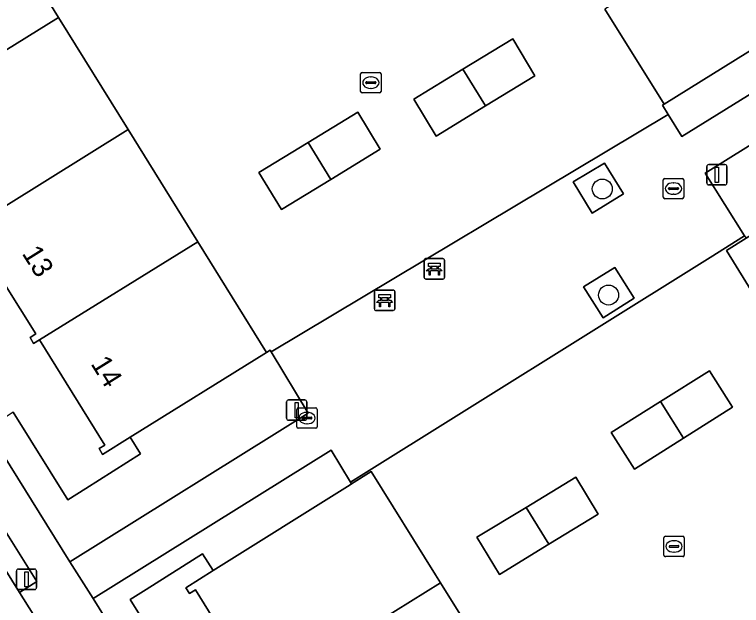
# Model space of a CAD drawing. Extents: x 159279 to 160377, y 384531 to 385888.
# Drawn here: x 159510.12 to 159545.75, y 385344.02 to 385373 of the extents above; entities that cross this region are included whole.
import ezdxf

# ---------------------------------------------------------------- set-up
doc = ezdxf.new("R2010")
doc.units = 0
for name, color, linetype in [('IMGEO_Bank', 7, 'Continuous'), ('IMGEO_Boom', 7, 'Continuous'), ('IMGEO_Erf', 7, 'Continuous'), ('IMGEO_Groenvoorziening', 7, 'Continuous'), ('IMGEO_Kolk', 7, 'Continuous'), ('IMGEO_Lichtmast', 7, 'Continuous'), ('IMGEO_Pand', 7, 'Continuous'), ('IMGEO_Pand_nummerreeks', 7, 'Continuous'), ('IMGEO_Rijbaan_lokaal_open', 7, 'Continuous'), ('IMGEO_Terreindeel_gesloten', 7, 'Continuous'), ('IMGEO_Voetpad_open', 7, 'Continuous')]:
    doc.layers.add(name, color=color, linetype=linetype)

msp = doc.modelspace()

# ---------------------------------------------------------------- linework, layer by layer
at = {"layer": 'IMGEO_Bank'}
for p, q in [((159530.199, 385360.104), (159530.199, 385360.945)), ((159530.199, 385360.945), (159530.199, 385360.104)), ((159530.274, 385361.029), (159531.115, 385361.029)), ((159531.115, 385361.029), (159530.274, 385361.029)), ((159531.199, 385360.954), (159531.199, 385360.113)), ((159531.199, 385360.113), (159531.199, 385360.954)), ((159530.896, 385360.427), (159530.503, 385360.427)), ((159530.508, 385360.535), (159530.508, 385360.641)), ((159530.552, 385360.641), (159530.552, 385360.535)), ((159530.84, 385360.647), (159530.558, 385360.647)), ((159530.558, 385360.529), (159530.84, 385360.529)), ((159530.846, 385360.535), (159530.846, 385360.641)), ((159530.89, 385360.641), (159530.89, 385360.535)), ((159531.124, 385360.029), (159530.283, 385360.029)), ((159530.283, 385360.029), (159531.124, 385360.029)), ((159527.764, 385358.564), (159527.764, 385359.405)), ((159527.764, 385359.405), (159527.764, 385358.564)), ((159527.839, 385359.489), (159528.68, 385359.489)), ((159528.68, 385359.489), (159527.839, 385359.489)), ((159528.764, 385359.414), (159528.764, 385358.573)), ((159528.764, 385358.573), (159528.764, 385359.414)), ((159528.073, 385358.995), (159528.073, 385359.101)), ((159528.117, 385359.101), (159528.117, 385358.995)), ((159528.405, 385359.107), (159528.123, 385359.107)), ((159528.123, 385358.989), (159528.405, 385358.989)), ((159528.411, 385358.995), (159528.411, 385359.101)), ((159528.455, 385359.101), (159528.455, 385358.995)), ((159528.461, 385358.887), (159528.068, 385358.887)), ((159528.689, 385358.489), (159527.848, 385358.489)), ((159527.848, 385358.489), (159528.689, 385358.489))]:
    msp.add_line(p, q, dxfattribs=at)
for points in [[(159530.502, 385360.647), (159530.416, 385360.647), (159530.416, 385360.808), (159530.979, 385360.808), (159530.979, 385360.647), (159530.896, 385360.647)], [(159530.446, 385360.427), (159530.304, 385360.427), (159530.416, 385360.529), (159530.502, 385360.529)], [(159530.496, 385360.42), (159530.496, 385360.213), (159530.453, 385360.213), (159530.453, 385360.42)], [(159530.896, 385360.529), (159530.979, 385360.529), (159531.091, 385360.427), (159530.952, 385360.427)], [(159530.946, 385360.42), (159530.946, 385360.213), (159530.902, 385360.213), (159530.902, 385360.42)], [(159528.067, 385359.107), (159527.981, 385359.107), (159527.981, 385359.268), (159528.544, 385359.268), (159528.544, 385359.107), (159528.461, 385359.107)], [(159528.011, 385358.887), (159527.869, 385358.887), (159527.981, 385358.989), (159528.067, 385358.989)], [(159528.461, 385358.989), (159528.544, 385358.989), (159528.656, 385358.887), (159528.517, 385358.887)], [(159528.061, 385358.88), (159528.061, 385358.673), (159528.018, 385358.673), (159528.018, 385358.88)], [(159528.511, 385358.88), (159528.511, 385358.673), (159528.467, 385358.673), (159528.467, 385358.88)]]:
    msp.add_lwpolyline(points, dxfattribs=at)
for centre, radius, start, end in [((159530.277, 385360.951), 0.0779, 92.4484, 184.2845), ((159530.277, 385360.951), 0.0779, 92.4484, 184.2845), ((159531.121, 385360.951), 0.0779, 2.4484, 94.2845), ((159531.121, 385360.951), 0.0779, 2.4484, 94.2845), ((159530.446, 385360.42), 0.00671, 2.8957, 87.1043), ((159530.503, 385360.42), 0.00671, 92.8957, 177.1043), ((159530.501, 385360.64), 0.00671, 2.8957, 87.1043), ((159530.501, 385360.536), 0.00671, 272.8957, 357.1043), ((159530.558, 385360.64), 0.00671, 92.8957, 177.1043), ((159530.558, 385360.536), 0.00671, 182.8957, 267.1043), ((159530.84, 385360.64), 0.00671, 2.8957, 87.1043), ((159530.84, 385360.536), 0.00671, 272.8957, 357.1043), ((159530.897, 385360.64), 0.00671, 92.8957, 177.1043), ((159530.897, 385360.536), 0.00671, 182.8957, 267.1043), ((159530.895, 385360.42), 0.00671, 2.8957, 87.1043), ((159530.952, 385360.42), 0.00671, 92.8957, 177.1043), ((159530.277, 385360.107), 0.0779, 182.4484, 274.2845), ((159530.277, 385360.107), 0.0779, 182.4484, 274.2845), ((159531.121, 385360.107), 0.0779, 272.4484, 4.2845), ((159531.121, 385360.107), 0.0779, 272.4484, 4.2845), ((159527.842, 385359.411), 0.0779, 92.4484, 184.2845), ((159527.842, 385359.411), 0.0779, 92.4484, 184.2845), ((159528.686, 385359.411), 0.0779, 2.4484, 94.2845), ((159528.686, 385359.411), 0.0779, 2.4484, 94.2845), ((159528.066, 385359.1), 0.00671, 2.8957, 87.1043), ((159528.066, 385358.996), 0.00671, 272.8957, 357.1043), ((159528.123, 385359.1), 0.00671, 92.8957, 177.1043), ((159528.123, 385358.996), 0.00671, 182.8957, 267.1043), ((159528.405, 385359.1), 0.00671, 2.8957, 87.1043), ((159528.405, 385358.996), 0.00671, 272.8957, 357.1043), ((159528.462, 385359.1), 0.00671, 92.8957, 177.1043), ((159528.462, 385358.996), 0.00671, 182.8957, 267.1043), ((159527.842, 385358.567), 0.0779, 182.4484, 274.2845), ((159527.842, 385358.567), 0.0779, 182.4484, 274.2845), ((159528.011, 385358.88), 0.00671, 2.8957, 87.1043), ((159528.068, 385358.88), 0.00671, 92.8957, 177.1043), ((159528.46, 385358.88), 0.00671, 2.8957, 87.1043), ((159528.517, 385358.88), 0.00671, 92.8957, 177.1043), ((159528.686, 385358.567), 0.0779, 272.4484, 4.2845), ((159528.686, 385358.567), 0.0779, 272.4484, 4.2845)]:
    msp.add_arc(centre, radius, start, end, dxfattribs=at)
at = {"layer": 'IMGEO_Boom'}
for centre in [(159538.932, 385364.446), (159539.24, 385359.245)]:
    msp.add_circle(centre, 0.489, dxfattribs=at)
at = {"layer": 'IMGEO_Erf'}
for points in [[(159508.971, 385378.179), (159512.272, 385372.863), (159515.691, 385367.355), (159519.102, 385361.861), (159522.472, 385356.434), (159522.653, 385356.547), (159522.704, 385356.461), (159542.167, 385368.097), (159541.884, 385368.557), (159541.969, 385368.61), (159539.064, 385373.265)], [(159510.061, 385353.497), (159512.737, 385349.205), (159513.619, 385349.761), (159516.301, 385351.454), (159515.795, 385352.272), (159514.431, 385351.421), (159514.264, 385351.717), (159514.545, 385351.888), (159511.339, 385357.041), (159511.055, 385356.868), (159510.882, 385357.158), (159511.164, 385357.337), (159508.002, 385362.379)], [(159545.911, 385362.141), (159544.219, 385361.084), (159526.589, 385350.077), (159526.643, 385349.992), (159527.598, 385350.585), (159530.751, 385345.531), (159530.995, 385345.14), (159534.332, 385339.79), (159537.665, 385334.447), (159541.091, 385328.956), (159544.511, 385323.473), (159547.84, 385318.137)], [(159546.45, 385359.131), (159545.022, 385361.424), (159545.983, 385362.027)]]:
    msp.add_lwpolyline(points, dxfattribs=at)
for points in [[(159532.101, 385370.326), (159534.539, 385371.81), (159535.626, 385369.995), (159533.211, 385368.516), (159530.795, 385367.036), (159529.689, 385368.858)], [(159524.515, 385366.729), (159526.953, 385368.213), (159528.04, 385366.398), (159525.625, 385364.919), (159523.209, 385363.439), (159522.103, 385365.261)], [(159540.509, 385350.712), (159539.375, 385352.511), (159541.785, 385354.025), (159544.186, 385355.533), (159545.323, 385353.739), (159542.916, 385352.226)], [(159538.724, 385348.503), (159536.308, 385347.024), (159533.893, 385345.544), (159532.787, 385347.366), (159535.199, 385348.834), (159537.637, 385350.318)]]:
    msp.add_lwpolyline(points, close=True, dxfattribs=at)
at = {"layer": 'IMGEO_Groenvoorziening'}
for points in [[(159552.306, 385379.406), (159549.83, 385377.84), (159551.76, 385374.716), (159550.773, 385374.1), (159541.969, 385368.61), (159541.884, 385368.557), (159542.167, 385368.097), (159542.83, 385367.018), (159555.238, 385374.72)], [(159556.351, 385372.911), (159552.599, 385370.593), (159543.979, 385365.226), (159545.911, 385362.141), (159545.983, 385362.027), (159549.656, 385364.332), (159554.867, 385367.58), (159555.774, 385368.145), (159557.757, 385364.996), (159560.291, 385366.59)], [(159539.04, 385365.72), (159537.509, 385364.793), (159538.438, 385363.263), (159539.974, 385364.206)], [(159539.549, 385360.593), (159538.008, 385359.643), (159538.98, 385358.125), (159540.493, 385359.091)], [(159503.017, 385356.459), (159510.367, 385344.653), (159511.207, 385345.192), (159503.848, 385356.959)], [(159522.704, 385356.461), (159522.653, 385356.547), (159522.472, 385356.434), (159515.795, 385352.272), (159516.301, 385351.454), (159513.619, 385349.761), (159512.737, 385349.205), (159510.061, 385353.497), (159509.655, 385353.244), (159508.766, 385352.691), (159512.828, 385346.166), (159524.507, 385353.448)], [(159526.567, 385349.945), (159526.643, 385349.992), (159526.589, 385350.077), (159525.637, 385351.642), (159513.967, 385344.361), (159516.864, 385339.703), (159517.725, 385340.259), (159518.148, 385340.532), (159516.872, 385342.583), (159515.793, 385344.318), (159516.58, 385344.813), (159519.338, 385346.547), (159519.862, 385345.731)]]:
    msp.add_lwpolyline(points, close=True, dxfattribs=at)
at = {"layer": 'IMGEO_Kolk'}
for p, q in [((159527.086, 385369.234), (159527.086, 385370.086)), ((159527.161, 385370.16), (159528.013, 385370.16)), ((159528.087, 385370.086), (159528.087, 385369.234)), ((159527.345, 385369.654), (159527.345, 385369.666)), ((159527.783, 385369.617), (159527.385, 385369.617)), ((159527.388, 385369.703), (159527.786, 385369.703)), ((159527.574, 385369.94), (159527.599, 385369.94)), ((159527.829, 385369.666), (159527.829, 385369.654)), ((159527.597, 385369.38), (159527.572, 385369.38)), ((159528.013, 385369.16), (159527.161, 385369.16)), ((159541.997, 385364.967), (159542.849, 385364.967)), ((159541.922, 385364.041), (159541.922, 385364.893)), ((159542.41, 385364.747), (159542.435, 385364.747)), ((159542.923, 385364.893), (159542.923, 385364.041)), ((159542.181, 385364.461), (159542.181, 385364.473)), ((159542.619, 385364.424), (159542.221, 385364.424)), ((159542.224, 385364.51), (159542.622, 385364.51)), ((159542.665, 385364.473), (159542.665, 385364.461)), ((159542.849, 385363.967), (159541.997, 385363.967)), ((159542.433, 385364.187), (159542.408, 385364.187)), ((159523.955, 385352.787), (159523.955, 385353.639)), ((159524.03, 385353.713), (159524.882, 385353.713)), ((159524.956, 385353.639), (159524.956, 385352.787)), ((159524.214, 385353.207), (159524.214, 385353.219)), ((159524.257, 385353.256), (159524.655, 385353.256)), ((159524.443, 385353.493), (159524.468, 385353.493)), ((159524.698, 385353.219), (159524.698, 385353.207)), ((159524.652, 385353.17), (159524.254, 385353.17)), ((159524.466, 385352.933), (159524.441, 385352.933)), ((159524.882, 385352.713), (159524.03, 385352.713)), ((159541.949, 385346.49), (159541.949, 385347.342)), ((159542.024, 385347.416), (159542.876, 385347.416)), ((159542.437, 385347.196), (159542.462, 385347.196)), ((159542.95, 385347.342), (159542.95, 385346.49)), ((159542.208, 385346.91), (159542.208, 385346.922)), ((159542.646, 385346.873), (159542.248, 385346.873)), ((159542.251, 385346.959), (159542.649, 385346.959)), ((159542.692, 385346.922), (159542.692, 385346.91)), ((159542.46, 385346.636), (159542.435, 385346.636)), ((159542.876, 385346.416), (159542.024, 385346.416))]:
    msp.add_line(p, q, dxfattribs=at)
for points in [[(159527.086, 385369.234), (159527.086, 385370.086)], [(159527.161, 385370.16), (159528.013, 385370.16)], [(159528.087, 385370.086), (159528.087, 385369.234)], [(159528.013, 385369.16), (159527.161, 385369.16)], [(159541.997, 385364.967), (159542.849, 385364.967)], [(159541.922, 385364.041), (159541.922, 385364.893)], [(159542.923, 385364.893), (159542.923, 385364.041)], [(159542.849, 385363.967), (159541.997, 385363.967)], [(159523.955, 385352.787), (159523.955, 385353.639)], [(159524.03, 385353.713), (159524.882, 385353.713)], [(159524.956, 385353.639), (159524.956, 385352.787)], [(159524.882, 385352.713), (159524.03, 385352.713)], [(159541.949, 385346.49), (159541.949, 385347.342)], [(159542.024, 385347.416), (159542.876, 385347.416)], [(159542.95, 385347.342), (159542.95, 385346.49)], [(159542.876, 385346.416), (159542.024, 385346.416)]]:
    msp.add_lwpolyline(points, dxfattribs=at)
for centre, radius, start, end in [((159527.163, 385370.084), 0.0765, 91.552, 178.448), ((159527.163, 385370.084), 0.0765, 91.552, 178.448), ((159528.011, 385370.084), 0.0765, 1.552, 88.448), ((159528.011, 385370.084), 0.0765, 1.552, 88.448), ((159527.385, 385369.663), 0.0403, 85.8775, 175.7526), ((159527.382, 385369.653), 0.0366, 178.938, 274.7102), ((159527.786, 385369.66), 0.043, 264.8664, 352.4533), ((159527.79, 385369.665), 0.0386, 1.7309, 96.639), ((159527.163, 385369.236), 0.0765, 181.552, 268.448), ((159527.163, 385369.236), 0.0765, 181.552, 268.448), ((159528.011, 385369.236), 0.0765, 271.552, 358.448), ((159528.011, 385369.236), 0.0765, 271.552, 358.448), ((159541.999, 385364.891), 0.0765, 91.552, 178.448), ((159541.999, 385364.891), 0.0765, 91.552, 178.448), ((159542.847, 385364.891), 0.0765, 1.552, 88.448), ((159542.847, 385364.891), 0.0765, 1.552, 88.448), ((159542.221, 385364.47), 0.0403, 85.8775, 175.7526), ((159542.218, 385364.46), 0.0366, 178.938, 274.7102), ((159542.622, 385364.467), 0.043, 264.8664, 352.4533), ((159542.626, 385364.472), 0.0386, 1.7309, 96.639), ((159541.999, 385364.043), 0.0765, 181.552, 268.448), ((159541.999, 385364.043), 0.0765, 181.552, 268.448), ((159542.847, 385364.043), 0.0765, 271.552, 358.448), ((159542.847, 385364.043), 0.0765, 271.552, 358.448), ((159524.032, 385353.637), 0.0765, 91.552, 178.448), ((159524.032, 385353.637), 0.0765, 91.552, 178.448), ((159524.88, 385353.637), 0.0765, 1.552, 88.448), ((159524.88, 385353.637), 0.0765, 1.552, 88.448), ((159524.254, 385353.216), 0.0403, 85.8775, 175.7526), ((159524.251, 385353.206), 0.0366, 178.938, 274.7102), ((159524.655, 385353.213), 0.043, 264.8664, 352.4533), ((159524.659, 385353.218), 0.0386, 1.7309, 96.639), ((159524.032, 385352.789), 0.0765, 181.552, 268.448), ((159524.032, 385352.789), 0.0765, 181.552, 268.448), ((159524.88, 385352.789), 0.0765, 271.552, 358.448), ((159524.88, 385352.789), 0.0765, 271.552, 358.448), ((159542.026, 385347.34), 0.0765, 91.552, 178.448), ((159542.026, 385347.34), 0.0765, 91.552, 178.448), ((159542.874, 385347.34), 0.0765, 1.552, 88.448), ((159542.874, 385347.34), 0.0765, 1.552, 88.448), ((159542.248, 385346.919), 0.0403, 85.8775, 175.7526), ((159542.245, 385346.909), 0.0366, 178.938, 274.7102), ((159542.649, 385346.916), 0.043, 264.8664, 352.4533), ((159542.653, 385346.921), 0.0386, 1.7309, 96.639), ((159542.026, 385346.492), 0.0765, 181.552, 268.448), ((159542.026, 385346.492), 0.0765, 181.552, 268.448), ((159542.874, 385346.492), 0.0765, 271.552, 358.448), ((159542.874, 385346.492), 0.0765, 271.552, 358.448)]:
    msp.add_arc(centre, radius, start, end, dxfattribs=at)
for centre, major_axis, ratio, start_param, end_param in [((159527.573, 385369.66), (-0.387, 0.002), 0.722429, 4.712389, 7.853982), ((159527.598, 385369.66), (-0.39, 0.002), 0.717154, 1.570796, 4.712389), ((159542.409, 385364.467), (-0.387, 0.002), 0.722429, 4.712389, 7.853982), ((159542.434, 385364.467), (-0.39, 0.002), 0.717154, 1.570796, 4.712389), ((159524.442, 385353.213), (-0.387, 0.002), 0.722429, 4.712389, 7.853982), ((159524.467, 385353.213), (-0.39, 0.002), 0.717154, 1.570796, 4.712389), ((159542.436, 385346.916), (-0.387, 0.002), 0.722429, 4.712389, 7.853982), ((159542.461, 385346.916), (-0.39, 0.002), 0.717154, 1.570796, 4.712389)]:
    msp.add_ellipse(centre, major_axis=major_axis, ratio=ratio, start_param=start_param, end_param=end_param, dxfattribs=at)
at = {"layer": 'IMGEO_Lichtmast'}
for p, q in [((159544.053, 385364.745), (159544.053, 385365.545)), ((159544.053, 385365.545), (159544.053, 385364.745)), ((159544.153, 385365.645), (159544.943, 385365.645)), ((159544.943, 385365.645), (159544.153, 385365.645)), ((159545.043, 385365.545), (159545.043, 385364.745)), ((159545.043, 385364.745), (159545.043, 385365.545)), ((159544.943, 385364.645), (159544.153, 385364.645)), ((159544.153, 385364.645), (159544.943, 385364.645)), ((159523.458, 385353.202), (159523.458, 385354.002)), ((159523.458, 385354.002), (159523.458, 385353.202)), ((159523.558, 385354.102), (159524.348, 385354.102)), ((159524.348, 385354.102), (159523.558, 385354.102)), ((159524.448, 385354.002), (159524.448, 385353.202)), ((159524.448, 385353.202), (159524.448, 385354.002)), ((159524.348, 385353.102), (159523.558, 385353.102)), ((159523.558, 385353.102), (159524.348, 385353.102)), ((159510.311, 385345.805), (159511.101, 385345.805)), ((159511.101, 385345.805), (159510.311, 385345.805)), ((159510.211, 385344.905), (159510.211, 385345.705)), ((159510.211, 385345.705), (159510.211, 385344.905)), ((159511.201, 385345.705), (159511.201, 385344.905)), ((159511.201, 385344.905), (159511.201, 385345.705)), ((159511.101, 385344.805), (159510.311, 385344.805)), ((159510.311, 385344.805), (159511.101, 385344.805))]:
    msp.add_line(p, q, dxfattribs=at)
for points in [[(159544.473, 385365.52), (159544.623, 385365.52), (159544.623, 385364.77), (159544.473, 385364.77), (159544.473, 385365.52)], [(159523.878, 385353.977), (159524.028, 385353.977), (159524.028, 385353.227), (159523.878, 385353.227), (159523.878, 385353.977)], [(159510.631, 385345.68), (159510.781, 385345.68), (159510.781, 385344.93), (159510.631, 385344.93), (159510.631, 385345.68)]]:
    msp.add_lwpolyline(points, dxfattribs=at)
for centre, start, end in [((159544.153, 385365.545), 90, 180), ((159544.153, 385365.545), 90, 180), ((159544.943, 385365.545), 0, 90), ((159544.943, 385365.545), 360, 90), ((159544.153, 385364.745), 180, 270), ((159544.153, 385364.745), 180, 270), ((159544.943, 385364.745), 270, 0), ((159544.943, 385364.745), 270, 0), ((159523.558, 385354.002), 90, 180), ((159523.558, 385354.002), 90, 180), ((159524.348, 385354.002), 0, 90), ((159524.348, 385354.002), 360, 90), ((159523.558, 385353.202), 180, 270), ((159523.558, 385353.202), 180, 270), ((159524.348, 385353.202), 270, 0), ((159524.348, 385353.202), 270, 0), ((159510.311, 385345.705), 90, 180), ((159510.311, 385345.705), 90, 180), ((159511.101, 385345.705), 0, 90), ((159511.101, 385345.705), 360, 90), ((159510.311, 385344.905), 180, 270), ((159510.311, 385344.905), 180, 270), ((159511.101, 385344.905), 270, 0), ((159511.101, 385344.905), 270, 0)]:
    msp.add_arc(centre, 0.1, start, end, dxfattribs=at)
at = {"layer": 'IMGEO_Pand'}
for points in [[(159550.773, 385374.1), (159549.19, 385376.653), (159549.47, 385376.825), (159549.29, 385377.084), (159549.012, 385376.913), (159547.857, 385378.754), (159539.064, 385373.265), (159541.969, 385368.61)], [(159508.971, 385378.179), (159501.165, 385373.333), (159500.904, 385373.164), (159501.059, 385372.896), (159501.33, 385373.071), (159504.502, 385368.039), (159512.272, 385372.863)], [(159512.272, 385372.863), (159504.502, 385368.039), (159504.212, 385367.85), (159504.374, 385367.579), (159504.651, 385367.741), (159507.83, 385362.678), (159507.547, 385362.501), (159507.634, 385362.352), (159515.691, 385367.355)], [(159532.101, 385370.326), (159533.211, 385368.516), (159535.626, 385369.995), (159534.539, 385371.81)], [(159533.211, 385368.516), (159532.101, 385370.326), (159529.689, 385368.858), (159530.795, 385367.036)], [(159524.515, 385366.729), (159525.625, 385364.919), (159528.04, 385366.398), (159526.953, 385368.213)], [(159557.752, 385362.931), (159556.624, 385364.736), (159556.902, 385364.907), (159556.729, 385365.191), (159556.45, 385365.023), (159554.867, 385367.58), (159549.656, 385364.332), (159545.983, 385362.027), (159545.022, 385361.424), (159546.45, 385359.131), (159547.913, 385356.788)], [(159515.691, 385367.355), (159507.634, 385362.352), (159507.714, 385362.215), (159508.002, 385362.379), (159511.164, 385357.337), (159510.882, 385357.158), (159511.055, 385356.868), (159511.339, 385357.041), (159519.102, 385361.861)], [(159524.515, 385366.729), (159522.103, 385365.261), (159523.209, 385363.439), (159525.625, 385364.919)], [(159522.472, 385356.434), (159519.102, 385361.861), (159511.339, 385357.041), (159514.545, 385351.888), (159514.264, 385351.717), (159514.431, 385351.421), (159515.795, 385352.272)], [(159545.323, 385353.739), (159544.186, 385355.533), (159541.785, 385354.025), (159542.916, 385352.226)], [(159541.785, 385354.025), (159539.375, 385352.511), (159540.509, 385350.712), (159542.916, 385352.226)], [(159527.598, 385350.585), (159526.643, 385349.992), (159526.567, 385349.945), (159519.862, 385345.731), (159518.525, 385344.89), (159518.698, 385344.614), (159518.995, 385344.793), (159522.171, 385339.635), (159530.995, 385345.14), (159530.751, 385345.531)], [(159535.199, 385348.834), (159536.308, 385347.024), (159538.724, 385348.503), (159537.637, 385350.318)], [(159536.308, 385347.024), (159535.199, 385348.834), (159532.787, 385347.366), (159533.893, 385345.544)], [(159534.332, 385339.79), (159530.995, 385345.14), (159522.171, 385339.635), (159521.895, 385339.464), (159522.061, 385339.196), (159522.355, 385339.363), (159525.505, 385334.283)]]:
    msp.add_lwpolyline(points, close=True, dxfattribs=at)
at = {"layer": 'IMGEO_Rijbaan_lokaal_open'}
msp.add_lwpolyline([(159520.255, 385328.8), (159519.469, 385330.043), (159514.691, 385337.689), (159513.916, 385338.953), (159511.503, 385342.85), (159510.367, 385344.653), (159503.017, 385356.459)], dxfattribs=at)
at = {"layer": 'IMGEO_Terreindeel_gesloten'}
msp.add_lwpolyline([(159522.171, 385339.635), (159518.995, 385344.793), (159518.698, 385344.614), (159518.525, 385344.89), (159519.862, 385345.731), (159519.338, 385346.547), (159516.58, 385344.813), (159515.793, 385344.318), (159516.872, 385342.583)], dxfattribs=at)
at = {"layer": 'IMGEO_Voetpad_open'}
for points in [[(159544.219, 385361.084), (159545.911, 385362.141), (159543.979, 385365.226), (159552.599, 385370.593), (159556.351, 385372.911), (159555.238, 385374.72), (159542.83, 385367.018), (159542.167, 385368.097), (159522.704, 385356.461), (159524.507, 385353.448), (159512.828, 385346.166), (159513.967, 385344.361), (159525.637, 385351.642), (159526.589, 385350.077)], [(159537.509, 385364.793), (159539.04, 385365.72), (159539.974, 385364.206), (159538.438, 385363.263)], [(159539.549, 385360.593), (159540.493, 385359.091), (159538.98, 385358.125), (159538.008, 385359.643)]]:
    msp.add_lwpolyline(points, close=True, dxfattribs=at)
for points in [[(159503.848, 385356.959), (159511.207, 385345.192), (159510.367, 385344.653), (159511.503, 385342.85), (159512.339, 385343.356), (159514.742, 385339.457), (159513.916, 385338.953), (159514.691, 385337.689), (159515.497, 385338.189), (159520.3, 385330.582), (159519.469, 385330.043), (159520.255, 385328.8), (159521.094, 385329.298), (159526.576, 385320.524)], [(159516.864, 385339.703), (159513.967, 385344.361), (159512.828, 385346.166), (159508.766, 385352.691)]]:
    msp.add_lwpolyline(points, dxfattribs=at)

# ---------------------------------------------------------------- texts
at = {"layer": 'IMGEO_Pand_nummerreeks'}
for s, rotation, p in [('13', 302.0912, (159510.459, 385361.285)), ('14', 301.8906, (159513.829, 385355.878))]:
    msp.add_text(s, height=1, rotation=rotation, dxfattribs=at).set_placement(p)

doc.saveas('drawing.dxf')
